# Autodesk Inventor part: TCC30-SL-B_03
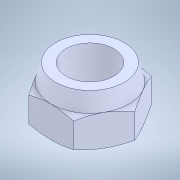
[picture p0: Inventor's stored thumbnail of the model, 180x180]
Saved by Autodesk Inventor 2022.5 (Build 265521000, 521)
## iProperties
Created: 2023-09
Part Number: TCC30-SL-B_03
Material: 一般
Document SubType Name: Modeling
Designer: ImaoCorp
Density: 1 g/cm^3
Appearance: 既定
Author: ImaoCorp
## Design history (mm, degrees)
feature "TCC30-SL-B_03"
node "ソリッド1"
